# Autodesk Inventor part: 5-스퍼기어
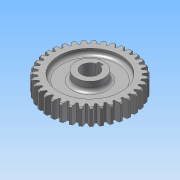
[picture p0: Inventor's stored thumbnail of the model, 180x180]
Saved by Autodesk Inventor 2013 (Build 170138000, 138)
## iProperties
Created: 2013-08
Part Number: 5-스퍼기어
Material: 강
Document SubType Name: Modeling
Designer: 한국산업디자인학원
Categories: <?xml version="1.0" encoding="UTF-16"?> <MemberInstance><Categories><FamilyTemplate><FamilyTemplateParameter ValueType="xs:double" Id="1" ObjectReferenceKey="da
Density: 1 g/cm^3
CustomPartVersion: 1
Author: 한국산업디자인학원
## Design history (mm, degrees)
sketch "Sketch1"
  geometry: C1 r 37 at (0, 0)
  constraints: 1 centre point
  dimensions: "d0" = 74 diameter of C1 (= da_da)
extrude "Extrusion1" new body sketch "Sketch1" distance "d1" = 15 (= da_b); taper "d2" = 0 deg
chamfer "모따기1" distance "d49" = 1; stored, may be unused: second distance "d50" = 2, angle "d51" = 45 deg
workplane "Work Plane2"
feature "피치 지름" dims "d4" = 10, "d5" = 0
workplane "Work Plane8"
workplane "Work Plane9"
feature "스퍼 기어" dims "da_b" = 15, "da_d" = 70, "da_aw" = 70, "da_da" = 74, "da_df" = 65, "da_dw" = 70, angle "da_beta" = 0 deg, "da_lefttooth" = 0, "da_righttooth" = 0
node "작업 평면11"
sketch "스케치3"
  geometry: C1 r 12.5 at (0, 0); 1 further point
  constraints: 1 centre point, 1 coincident
  dimensions: "d53" = 25 diameter of C1
extrude "돌출2" join sketch "스케치3" distance "d55" = 31; taper "d56" = 0 deg
sketch "스케치4"
  geometry: L1 (-2, 7.228)-(-2, 9.8); L2 (-2, 9.8)-(2, 9.8); L3 (2, 9.8)-(2, 7.228); C1 r 12.5 at (0, 0) reference; A1 r 7.5 centre (0, 0) between (-2, 7.228) and (2, 7.228); 1 further point
  constraints: 6 end point, 2 parallel, 2 point on circle, 1 centre point, 1 coincident, 1 midpoint, 1 perpendicular, 1 vertical, 1 vertical alignment
  dimensions: "d57" = 15 diameter of A1; "d59" = 4 distance of L1.end L2.end; "d60" = 17.3 dimension on A1 L2
extrude "돌출3" cut sketch "스케치4" stored distance "d61" = 31; taper "d62" = 0 deg
sketch "스케치5"
  geometry: C1 r 12.5 at (0, 0) reference; C2 r 27.5 at (0, 0); A1 r 36 centre (0, 0) between (-5.215, 35.62) and (-7.633, 35.181) reference
  constraints: 1 centre point, 1 coincident
  dimensions: "d63" = 55 diameter of C2
extrude "돌출4" cut sketch "스케치5" distance "d65" = 5; taper "d66" = 0 deg
sketch "스케치6"
  geometry: C1 r 12.5 at (0, 0) reference; C2 r 27.5 at (0, 0); A1 r 32.5 centre (0, 0) between (9.347, 31.127) and (7.941, 31.515) reference
  constraints: 1 centre point, 1 coincident
  dimensions: "d67" = 55 diameter of C2
extrude "돌출5" cut sketch "스케치6" distance "d69" = 5; taper "d70" = 0 deg
fillet "모깎기2" dims "d72" = 3
fillet "모깎기3" dims "d73" = 3
body "Solid1"
sketch "Sketch2"
  geometry: C1 r 37 at (0, 0) reference; C2 r 35 at (0, 0)
  constraints: 1 centre point, 1 coincident
  dimensions: "d3" = 70 diameter of C2 (= da_dw)
body "Srf1"
other parameters: "d17" = 0, "d34" = 0.8976 (computed from da_z), "d39" = 0, "d41" = 0, "d47" = 0, "d48" = 0, "d52" = 3
